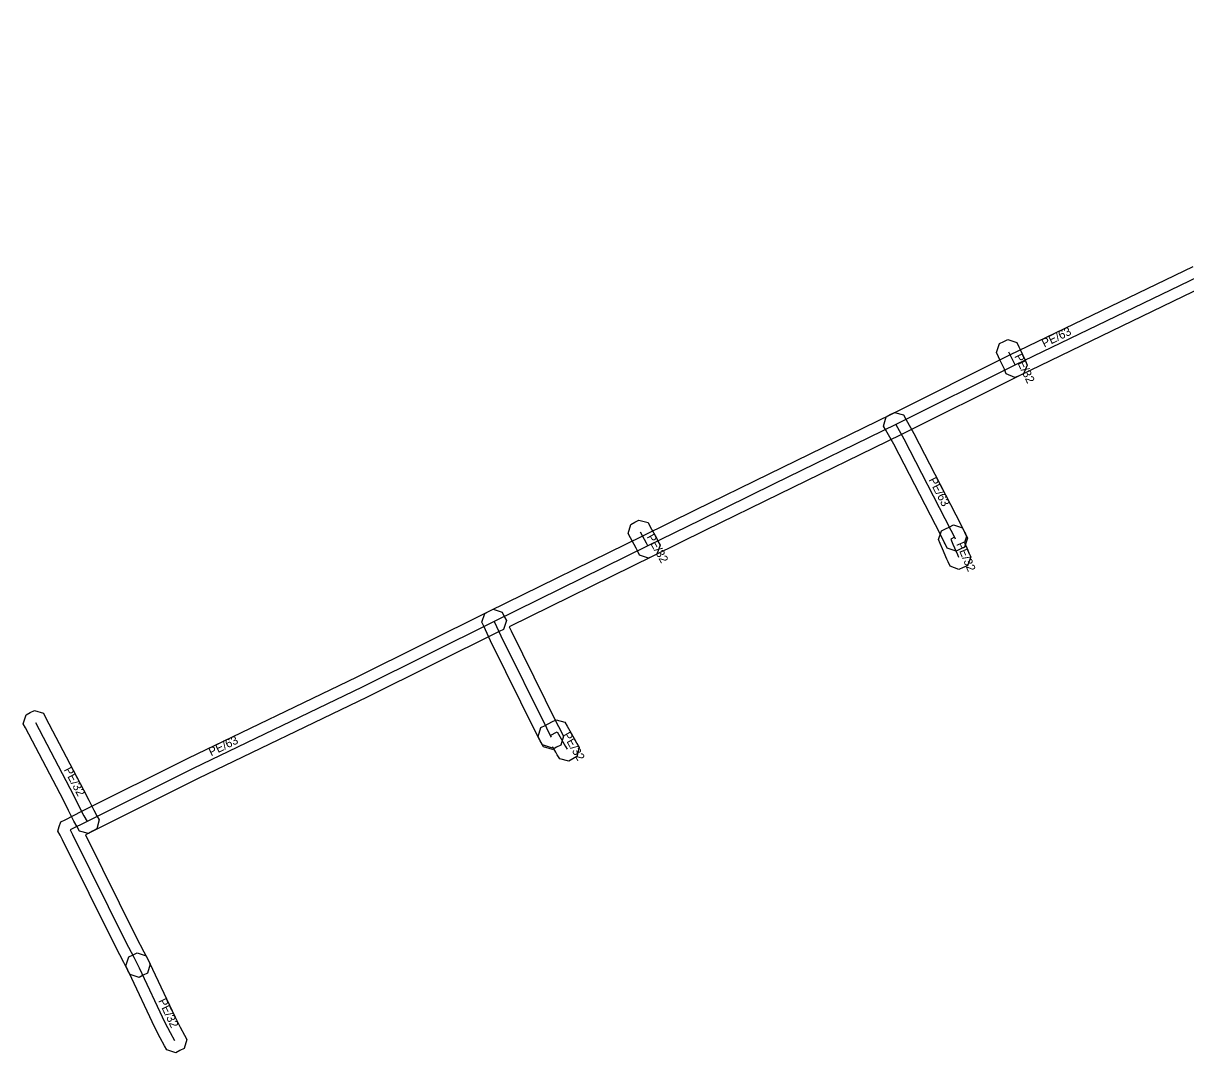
# Model space of a CAD drawing. Extents: x -574390 to -573768, y -1190959 to -1190603.
# Drawn here: x -573973.3 to -573870.9, y -1190918.6 to -1190827.9 of the extents above; entities that cross this region are included whole.
import ezdxf

# ---------------------------------------------------------------- set-up
doc = ezdxf.new("R2010")
doc.units = 0
for name, color, linetype in [('1', 7, 'Continuous'), ('24', 7, 'Continuous'), ('30', 7, 'Continuous')]:
    doc.layers.add(name, color=color, linetype=linetype)

msp = doc.modelspace()

# ---------------------------------------------------------------- linework, layer by layer
at = {"layer": '1'}
msp.add_lwpolyline([(-573869.377, -1190851.137), (-573885.509, -1190858.928), (-573895.998, -1190864.157), (-573906.73, -1190869.388), (-573913.204, -1190872.569), (-573917.849, -1190874.848), (-573930.501, -1190881.066), (-573930.328, -1190881.437), (-573926.329, -1190889.517), (-573925.986, -1190890.173), (-573925.908, -1190890.319), (-573925.713, -1190890.685), (-573925.954, -1190891.477), (-573926.319, -1190891.672), (-573926.685, -1190891.867), (-573927.477, -1190891.626), (-573927.672, -1190891.261), (-573927.754, -1190891.107), (-573928.111, -1190890.423), (-573932.132, -1190882.303), (-573932.727, -1190881.021), (-573932.899, -1190880.651), (-573932.627, -1190879.883), (-573932.261, -1190879.703), (-573918.731, -1190873.052), (-573914.086, -1190870.773), (-573907.61, -1190867.592), (-573896.882, -1190862.363), (-573886.391, -1190857.132), (-573870.263, -1190849.343)], dxfattribs=at)
for points in [[(-573885.787, -1190856.045), (-573885.608, -1190856.419), (-573885.498, -1190856.649), (-573885.054, -1190857.578), (-573885.022, -1190857.659), (-573884.868, -1190858.043), (-573885.194, -1190858.804), (-573885.579, -1190858.958), (-573885.963, -1190859.112), (-573886.724, -1190858.786), (-573886.878, -1190858.401), (-573886.886, -1190858.382), (-573887.302, -1190857.511), (-573887.412, -1190857.281), (-573887.591, -1190856.907), (-573887.315, -1190856.127), (-573886.941, -1190855.948), (-573886.567, -1190855.769)], [(-573895.77, -1190862.41), (-573895.567, -1190862.771), (-573894.859, -1190864.036), (-573890.697, -1190872.11), (-573890.388, -1190872.735), (-573890.313, -1190872.888), (-573890.13, -1190873.259), (-573890.396, -1190874.044), (-573890.768, -1190874.227), (-573891.139, -1190874.41), (-573891.924, -1190874.144), (-573892.107, -1190873.772), (-573892.182, -1190873.621), (-573892.483, -1190873.01), (-573896.621, -1190864.984), (-573897.313, -1190863.749), (-573897.515, -1190863.387), (-573897.29, -1190862.59), (-573896.929, -1190862.387), (-573896.567, -1190862.185)], [(-573919.013, -1190874.756), (-573919.192, -1190874.383), (-573919.299, -1190874.158), (-573919.815, -1190873.223), (-573920.015, -1190872.861), (-573919.786, -1190872.065), (-573919.423, -1190871.865), (-573919.061, -1190871.665), (-573918.265, -1190871.894), (-573918.065, -1190872.257), (-573917.521, -1190873.242), (-573917.388, -1190873.517), (-573917.209, -1190873.891), (-573917.484, -1190874.673), (-573917.857, -1190874.852), (-573918.231, -1190875.031)], [(-573890.205, -1190873.103), (-573890.386, -1190873.644), (-573890.101, -1190874.315), (-573890.003, -1190874.541), (-573889.838, -1190874.921), (-573890.141, -1190875.692), (-573890.521, -1190875.857), (-573890.901, -1190876.022), (-573891.672, -1190875.719), (-573891.837, -1190875.339), (-573891.939, -1190875.105), (-573892.327, -1190874.188), (-573892.524, -1190873.746), (-573892.687, -1190873.379), (-573892.415, -1190872.624), (-573892.056, -1190872.445), (-573891.731, -1190872.283), (-573891.36, -1190872.098), (-573890.575, -1190872.361), (-573890.39, -1190872.732)], [(-573967.222, -1190899.094), (-573967.809, -1190899.389), (-573963.349, -1190908.386), (-573962.664, -1190909.698), (-573962.299, -1190910.399), (-573962.108, -1190910.766), (-573962.357, -1190911.557), (-573962.724, -1190911.748), (-573963.091, -1190911.939), (-573963.882, -1190911.69), (-573964.073, -1190911.323), (-573964.438, -1190910.622), (-573965.131, -1190909.294), (-573969.829, -1190899.819), (-573970.041, -1190899.423), (-573970.241, -1190899.051), (-573970.114, -1190898.649), (-573969.986, -1190898.246), (-573969.61, -1190898.057), (-573968.118, -1190897.306), (-573958.77, -1190892.642), (-573943.879, -1190885.482), (-573932.265, -1190879.705), (-573931.894, -1190879.52), (-573931.109, -1190879.784), (-573930.925, -1190880.155), (-573930.74, -1190880.526), (-573931.004, -1190881.311), (-573931.375, -1190881.495), (-573943.001, -1190887.278), (-573957.89, -1190894.438)], [(-573971.518, -1190888.678), (-573971.325, -1190889.045), (-573967.97, -1190895.434), (-573967.517, -1190896.341), (-573967.067, -1190897.23), (-573966.797, -1190897.711), (-573966.595, -1190898.073), (-573966.82, -1190898.87), (-573967.181, -1190899.073), (-573967.543, -1190899.275), (-573968.34, -1190899.05), (-573968.543, -1190898.689), (-573968.833, -1190898.17), (-573969.303, -1190897.239), (-573969.75, -1190896.346), (-573973.095, -1190889.975), (-573973.288, -1190889.608), (-573973.042, -1190888.818), (-573972.675, -1190888.625), (-573972.308, -1190888.432)], [(-573926.395, -1190892.101), (-573926.652, -1190891.655), (-573926.772, -1190891.718), (-573927.563, -1190891.472), (-573927.756, -1190891.105), (-573927.948, -1190890.738), (-573927.702, -1190889.947), (-573927.335, -1190889.754), (-573926.725, -1190889.434), (-573926.365, -1190889.246), (-573925.587, -1190889.477), (-573925.388, -1190889.831), (-573925.16, -1190890.236), (-573924.665, -1190891.099), (-573924.526, -1190891.336), (-573924.317, -1190891.694), (-573924.528, -1190892.495), (-573924.886, -1190892.704), (-573925.244, -1190892.913), (-573926.045, -1190892.702), (-573926.254, -1190892.344)], [(-573962.467, -1190910.052), (-573962.286, -1190910.425), (-573962.17, -1190910.665), (-573959.916, -1190915.451), (-573959.457, -1190916.311), (-573959.076, -1190917.033), (-573958.883, -1190917.4), (-573959.127, -1190918.191), (-573959.493, -1190918.384), (-573959.86, -1190918.577), (-573960.651, -1190918.333), (-573960.844, -1190917.967), (-573961.223, -1190917.249), (-573961.704, -1190916.349), (-573963.974, -1190911.527), (-573964.086, -1190911.297), (-573964.267, -1190910.925), (-573963.995, -1190910.142), (-573963.622, -1190909.961), (-573963.25, -1190909.78)]]:
    msp.add_lwpolyline(points, close=True, dxfattribs=at)
at = {"layer": '24'}
for points in [[(-573824.15, -1190827.92), (-573828.05, -1190829.96), (-573839.1, -1190835.18), (-573850.29, -1190840.71), (-573851.881, -1190841.464), (-573860.86, -1190845.72), (-573869.82, -1190850.24), (-573885.95, -1190858.03), (-573896.44, -1190863.26), (-573907.17, -1190868.49), (-573913.645, -1190871.671), (-573918.29, -1190873.95), (-573931.82, -1190880.6), (-573931.23, -1190881.87), (-573927.22, -1190889.97), (-573926.87, -1190890.64), (-573926.79, -1190890.79)], [(-573886.51, -1190856.85), (-573886.4, -1190857.08), (-573885.97, -1190857.98), (-573885.95, -1190858.03)], [(-573896.44, -1190863.26), (-573895.74, -1190864.51), (-573891.59, -1190872.56), (-573891.285, -1190873.178), (-573891.21, -1190873.33)], [(-573918.29, -1190873.95), (-573918.41, -1190873.7), (-573918.94, -1190872.74)], [(-573891.285, -1190873.178), (-573891.61, -1190873.34), (-573891.41, -1190873.79), (-573891.02, -1190874.71), (-573890.92, -1190874.94)], [(-573931.82, -1190880.6), (-573943.44, -1190886.38), (-573958.33, -1190893.54), (-573967.67, -1190898.2), (-573969.16, -1190898.95), (-573968.94, -1190899.36), (-573964.24, -1190908.84), (-573963.551, -1190910.16), (-573963.186, -1190910.861)], [(-573972.21, -1190889.51), (-573968.86, -1190895.89), (-573968.41, -1190896.79), (-573967.95, -1190897.7), (-573967.67, -1190898.2)], [(-573926.87, -1190890.64), (-573926.26, -1190890.32), (-573926.03, -1190890.73), (-573925.53, -1190891.6), (-573925.39, -1190891.84)], [(-573963.186, -1190910.861), (-573963.072, -1190911.096), (-573960.81, -1190915.9), (-573960.34, -1190916.78), (-573959.96, -1190917.5)]]:
    msp.add_lwpolyline(points, dxfattribs=at)

# ---------------------------------------------------------------- texts
at = {"layer": '30'}
for s, rotation, p in [('PE/63', 25.77826721, (-573883.375315, -1190856.489963)), ('PE/32', 295.53743439, (-573886.028347, -1190857.239274)), ('PE/63', 297.27237055, (-573893.573597, -1190868.124348)), ('PE/32', 298.90235704, (-573918.407986, -1190873.141384)), ('PE/32', 292.97272133, (-573891.133021, -1190873.771591)), ('PE/63', 25.68102295, (-573956.741817, -1190892.480135)), ('PE/32', 299.88652694, (-573925.799518, -1190890.583038)), ('PE/32', 297.70299275, (-573969.730889, -1190893.650515)), ('PE/32', 295.21375854, (-573961.410729, -1190913.999425))]:
    msp.add_text(s, height=0.75, rotation=rotation, dxfattribs=at).set_placement(p)

doc.saveas('drawing.dxf')
